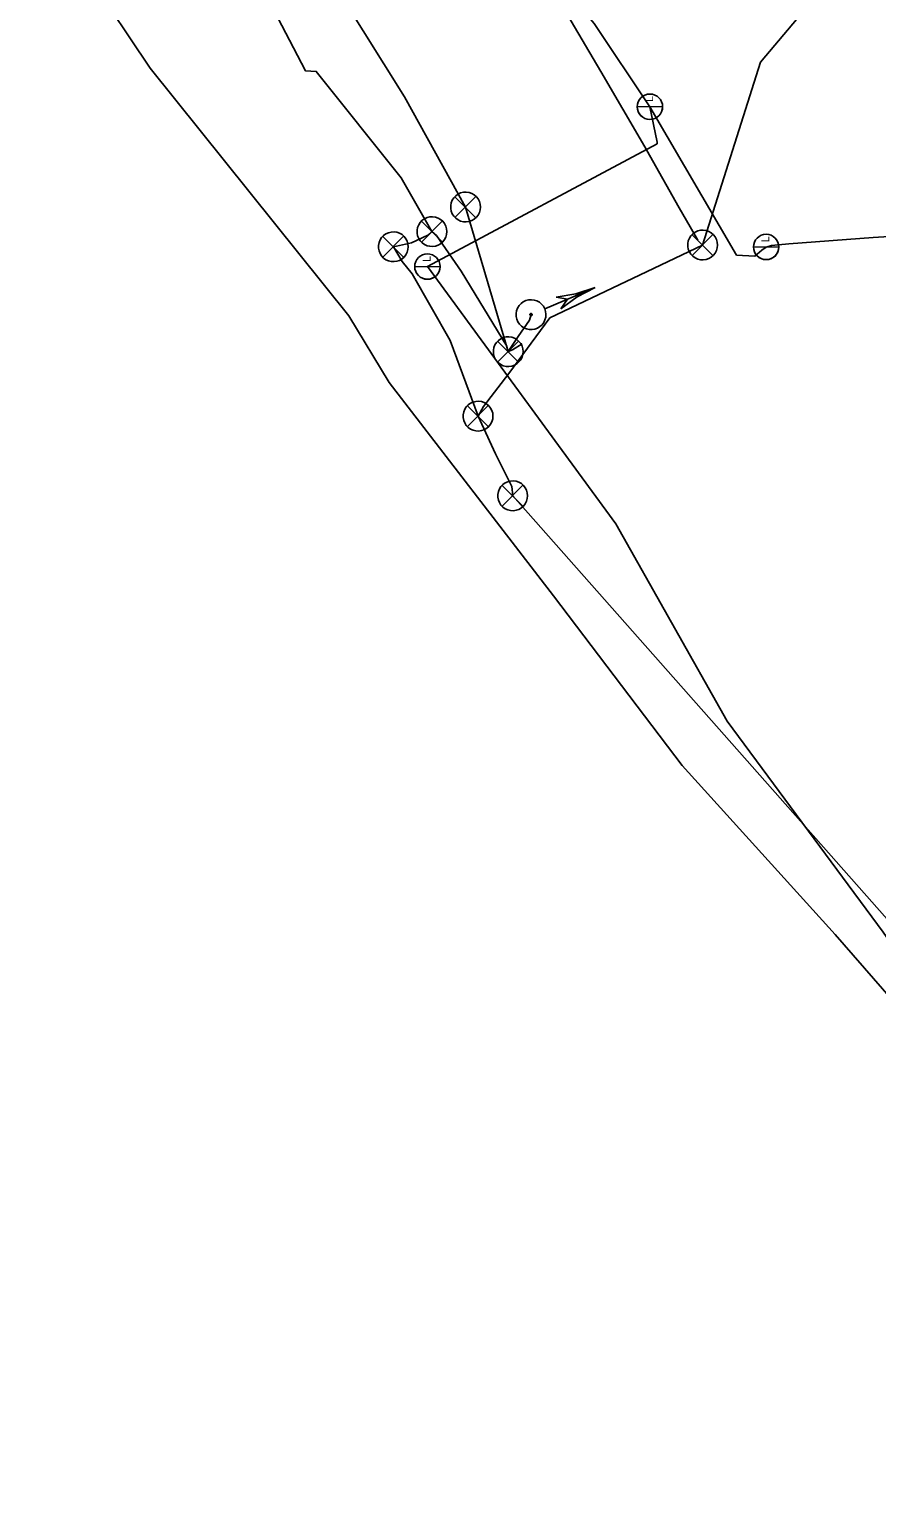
# Model space of a CAD drawing. Extents: x 596028 to 606371, y 330010 to 403088.
# Drawn here: x 604008 to 604195.4, y 338728.3 to 339055.2 of the extents above; entities that cross this region are included whole.
import ezdxf

# ---------------------------------------------------------------- set-up
doc = ezdxf.new("R2010")
doc.units = 0
for name, color, linetype in [('E_FTMS', 7, 'Continuous'), ('E_FTMS_Conduit', 7, 'Continuous'), ('E_LTG', 7, 'Continuous'), ('E_LTG_CID', 7, 'Continuous'), ('E_UTL_FO_UG_QWEST', 7, 'Continuous')]:
    doc.layers.add(name, color=color, linetype=linetype)

# ---------------------------------------------------------------- blocks, each defined once
blk = doc.blocks.new('_U286')
at = {"layer": 'E_LTG'}
blk.add_lwpolyline([(0.001, -0.171), (0.001, 0.172)], dxfattribs=at)
blk.add_circle((0.001, 0), 0.171, dxfattribs=at)
blk.add_arc((0.001, 0), 0.171, 90, 270, dxfattribs=at)
blk.add_text('L', height=0.108, dxfattribs=at).set_placement((0.066, -0.042))

msp = doc.modelspace()

# ---------------------------------------------------------------- linework, layer by layer
at = {"layer": 'E_FTMS'}
for points in [[(604107.76, 339015.89), (604107.7, 339016.52), (604107.53, 339017.12), (604107.24, 339017.68), (604106.85, 339018.17), (604106.38, 339018.58), (604105.83, 339018.89), (604105.24, 339019.1), (604104.62, 339019.19), (604103.99, 339019.16), (604103.38, 339019.01), (604102.81, 339018.75), (604102.3, 339018.39), (604101.87, 339017.93), (604101.53, 339017.41), (604101.3, 339016.82), (604101.18, 339016.21), (604101.18, 339015.58), (604101.3, 339014.96), (604101.53, 339014.38), (604101.87, 339013.85), (604102.3, 339013.4), (604102.81, 339013.04), (604103.38, 339012.77), (604103.99, 339012.63), (604104.62, 339012.6), (604105.24, 339012.69), (604105.83, 339012.89), (604106.38, 339013.21), (604106.85, 339013.62), (604107.24, 339014.11), (604107.53, 339014.67), (604107.7, 339015.27), (604107.76, 339015.89)], [(604106.73, 339018.23), (604102.12, 339013.57)], [(604102.12, 339018.18), (604106.77, 339013.53)], [(604100.32, 339010.46), (604100.26, 339011.09), (604100.09, 339011.69), (604099.8, 339012.25), (604099.41, 339012.74), (604098.94, 339013.15), (604098.39, 339013.46), (604097.8, 339013.67), (604097.18, 339013.76), (604096.55, 339013.73), (604095.94, 339013.58), (604095.37, 339013.32), (604094.86, 339012.96), (604094.43, 339012.5), (604094.09, 339011.98), (604093.86, 339011.39), (604093.74, 339010.78), (604093.74, 339010.15), (604093.86, 339009.53), (604094.09, 339008.95), (604094.43, 339008.42), (604094.86, 339007.97), (604095.37, 339007.61), (604095.94, 339007.34), (604096.55, 339007.2), (604097.18, 339007.17), (604097.8, 339007.26), (604098.39, 339007.46), (604098.94, 339007.78), (604099.41, 339008.19), (604099.8, 339008.68), (604100.09, 339009.24), (604100.26, 339009.84), (604100.32, 339010.46)], [(604099.29, 339012.8), (604094.68, 339008.14)], [(604094.68, 339012.75), (604099.33, 339008.1)], [(604091.78, 339007.1), (604091.72, 339007.73), (604091.55, 339008.33), (604091.26, 339008.89), (604090.87, 339009.38), (604090.4, 339009.79), (604089.85, 339010.1), (604089.26, 339010.31), (604088.64, 339010.4), (604088.01, 339010.37), (604087.4, 339010.22), (604086.83, 339009.96), (604086.32, 339009.6), (604085.89, 339009.14), (604085.55, 339008.61), (604085.32, 339008.03), (604085.2, 339007.42), (604085.2, 339006.79), (604085.32, 339006.17), (604085.55, 339005.59), (604085.89, 339005.06), (604086.32, 339004.61), (604086.83, 339004.24), (604087.4, 339003.98), (604088.01, 339003.84), (604088.64, 339003.81), (604089.26, 339003.9), (604089.85, 339004.1), (604090.4, 339004.41), (604090.87, 339004.82), (604091.26, 339005.32), (604091.55, 339005.88), (604091.72, 339006.48), (604091.78, 339007.1)], [(604090.74, 339009.44), (604086.13, 339004.78)], [(604086.13, 339009.39), (604090.79, 339004.74)], [(604160.22, 339007.49), (604160.16, 339008.12), (604159.99, 339008.72), (604159.7, 339009.28), (604159.31, 339009.77), (604158.84, 339010.18), (604158.3, 339010.49), (604157.7, 339010.7), (604157.08, 339010.79), (604156.45, 339010.76), (604155.85, 339010.61), (604155.27, 339010.35), (604154.76, 339009.99), (604154.33, 339009.53), (604153.99, 339009), (604153.76, 339008.42), (604153.64, 339007.81), (604153.64, 339007.18), (604153.76, 339006.56), (604153.99, 339005.98), (604154.33, 339005.45), (604154.76, 339005), (604155.27, 339004.63), (604155.85, 339004.37), (604156.45, 339004.23), (604157.08, 339004.2), (604157.7, 339004.29), (604158.3, 339004.49), (604158.84, 339004.8), (604159.31, 339005.22), (604159.7, 339005.71), (604159.99, 339006.27), (604160.16, 339006.87), (604160.22, 339007.49)], [(604159.19, 339009.83), (604154.58, 339005.17)], [(604154.58, 339009.78), (604159.23, 339005.13)], [(604121.99, 338993.37), (604121.69, 338993.92), (604121.29, 338994.41), (604120.81, 338994.81), (604120.26, 338995.11), (604119.66, 338995.3), (604119.04, 338995.38), (604118.42, 338995.34), (604117.81, 338995.18), (604117.24, 338994.91), (604116.74, 338994.53), (604116.32, 338994.07), (604115.99, 338993.53), (604115.77, 338992.95), (604115.66, 338992.33), (604115.67, 338991.7), (604115.81, 338991.09), (604116.05, 338990.51), (604116.4, 338989.99), (604116.84, 338989.54), (604117.36, 338989.19), (604117.94, 338988.94), (604118.55, 338988.81), (604119.18, 338988.79), (604119.8, 338988.89), (604120.39, 338989.11), (604120.92, 338989.43), (604121.39, 338989.85), (604121.76, 338990.36), (604122.04, 338990.92), (604122.21, 338991.52), (604122.25, 338992.15), (604122.18, 338992.77), (604121.99, 338993.37)], [(604133.13, 338998.1), (604122.04, 338993.39)], [(604133.13, 338998.1), (604128.89, 338996.68), (604124.49, 338995.93)], [(604127.05, 338995.52), (604124.49, 338995.93)], [(604125.56, 338993.4), (604127.05, 338995.52)], [(604133.13, 338998.1), (604129.16, 338996.04), (604125.57, 338993.39)], [(604119.19, 338992.18), (604119.16, 338992.22), (604119.13, 338992.26), (604119.09, 338992.29), (604119.05, 338992.31), (604119.01, 338992.33), (604118.96, 338992.33), (604118.91, 338992.33), (604118.87, 338992.32), (604118.82, 338992.3), (604118.78, 338992.27), (604118.75, 338992.23), (604118.73, 338992.19), (604118.71, 338992.15), (604118.7, 338992.1), (604118.7, 338992.05), (604118.71, 338992.01), (604118.73, 338991.96), (604118.76, 338991.92), (604118.79, 338991.89), (604118.83, 338991.86), (604118.88, 338991.84), (604118.92, 338991.83), (604118.97, 338991.83), (604119.02, 338991.84), (604119.06, 338991.85), (604119.1, 338991.88), (604119.14, 338991.91), (604119.17, 338991.95), (604119.19, 338991.99), (604119.2, 338992.04), (604119.21, 338992.09), (604119.2, 338992.13), (604119.19, 338992.18)], [(604117.19, 338983.89), (604117.13, 338984.52), (604116.96, 338985.12), (604116.67, 338985.68), (604116.28, 338986.17), (604115.81, 338986.58), (604115.26, 338986.89), (604114.67, 338987.1), (604114.05, 338987.19), (604113.42, 338987.16), (604112.81, 338987.01), (604112.24, 338986.75), (604111.73, 338986.39), (604111.3, 338985.93), (604110.96, 338985.41), (604110.73, 338984.82), (604110.61, 338984.21), (604110.61, 338983.58), (604110.73, 338982.96), (604110.96, 338982.38), (604111.3, 338981.85), (604111.73, 338981.4), (604112.24, 338981.04), (604112.81, 338980.77), (604113.42, 338980.63), (604114.05, 338980.6), (604114.67, 338980.69), (604115.26, 338980.89), (604115.81, 338981.21), (604116.28, 338981.62), (604116.67, 338982.11), (604116.96, 338982.67), (604117.13, 338983.27), (604117.19, 338983.89)], [(604116.16, 338986.23), (604111.55, 338981.57)], [(604111.55, 338986.18), (604116.2, 338981.53)], [(604110.53, 338969.61), (604110.47, 338970.24), (604110.29, 338970.84), (604110, 338971.4), (604109.62, 338971.89), (604109.14, 338972.3), (604108.6, 338972.62), (604108.01, 338972.82), (604107.39, 338972.91), (604106.76, 338972.88), (604106.15, 338972.73), (604105.58, 338972.47), (604105.07, 338972.11), (604104.63, 338971.65), (604104.3, 338971.13), (604104.06, 338970.54), (604103.94, 338969.93), (604103.94, 338969.3), (604104.06, 338968.68), (604104.3, 338968.1), (604104.63, 338967.57), (604105.07, 338967.12), (604105.58, 338966.76), (604106.15, 338966.5), (604106.76, 338966.35), (604107.39, 338966.32), (604108.01, 338966.41), (604108.6, 338966.61), (604109.14, 338966.93), (604109.62, 338967.34), (604110, 338967.83), (604110.29, 338968.39), (604110.47, 338968.99), (604110.53, 338969.61)], [(604109.49, 338971.95), (604104.88, 338967.29)], [(604104.88, 338971.9), (604109.53, 338967.25)], [(604118.19, 338951.98), (604118.13, 338952.61), (604117.96, 338953.21), (604117.67, 338953.77), (604117.28, 338954.26), (604116.81, 338954.67), (604116.26, 338954.98), (604115.67, 338955.19), (604115.05, 338955.28), (604114.42, 338955.25), (604113.81, 338955.1), (604113.24, 338954.84), (604112.73, 338954.48), (604112.3, 338954.02), (604111.96, 338953.49), (604111.73, 338952.91), (604111.61, 338952.3), (604111.61, 338951.67), (604111.73, 338951.05), (604111.96, 338950.47), (604112.3, 338949.94), (604112.73, 338949.49), (604113.24, 338949.12), (604113.81, 338948.86), (604114.42, 338948.72), (604115.05, 338948.69), (604115.67, 338948.78), (604116.26, 338948.98), (604116.81, 338949.29), (604117.28, 338949.71), (604117.67, 338950.2), (604117.96, 338950.76), (604118.13, 338951.36), (604118.19, 338951.98)], [(604117.16, 338954.32), (604112.55, 338949.66)], [(604112.55, 338954.27), (604117.2, 338949.62)]]:
    msp.add_lwpolyline(points, dxfattribs=at)
at = {"layer": 'E_FTMS_Conduit'}
for points in [[(604113.89, 338983.89), (604104.46, 339015.89), (604090.96, 339040.27), (604077.26, 339062.3), (604070.63, 339081.86), (604055.37, 339128.14), (604048.99, 339151), (604037.26, 339191.41), (604036.51, 339193.09), (604036.31, 339194.34), (604031.92, 339203.07), (604031.51, 339204.01), (604023.3, 339242.34), (604034.29, 339302.44)], [(604114.89, 338951.98), (604114.71, 338954.06), (604111.09, 338961.25), (604108.03, 338967.81), (604107.23, 338969.61), (604101.02, 338986.39), (604092.64, 339001.09), (604090.42, 339003.87), (604088.48, 339007.1), (604092.52, 339007.97), (604096.15, 339009.66), (604097.02, 339010.46), (604090.2, 339022.33), (604071.41, 339045.9), (604069.03, 339046.05), (604046.26, 339089.82)], [(604107.23, 338969.61), (604108.46, 338971.77), (604114.04, 338979.08), (604123.12, 338991.37), (604156.9, 339007.45), (604169.73, 339047.96), (604189.24, 339071.12), (604191.75, 339074.79)], [(604155.89, 339008.54), (604154.16, 339011.54), (604151.73, 339015.73), (604145.16, 339027.38), (604144.11, 339029.2), (604134.43, 339045.93), (604121.03, 339068.62)], [(604097.02, 339010.46), (604098, 339009.56), (604103.51, 339001.68), (604113.6, 338985.12), (604113.89, 338983.89)], [(604113.89, 338983.89), (604116.14, 338987.21), (604118.61, 338990.87), (604118.95, 338992.08)], [(604292.05, 338601.41), (604273.29, 338719.32), (604255.92, 338774.24), (604233.24, 338818.17), (604114.89, 338951.98)]]:
    msp.add_lwpolyline(points, dxfattribs=at)
at = {"layer": 'E_LTG_CID'}
msp.add_line((604146.89, 339029.9), (604096.01, 339002.71), dxfattribs=at)
for points in [[(604146.89, 339029.9), (604146.87, 339030.26), (604145.25, 339038.09), (604132.95, 339056.55), (604122.27, 339069.3), (604109.66, 339096.83), (604097.38, 339128.84), (604088.94, 339157.84), (604080.55, 339185.67), (604082.3, 339195.71), (604082.73, 339213.69), (604082.53, 339214.94)], [(604294.42, 339025.92), (604226.93, 339010.91), (604225.04, 339011.09), (604194.7, 339009.16), (604175.97, 339007.72), (604172.17, 339007.37), (604170.97, 339007.05), (604170.02, 339006.34), (604168.49, 339005.05), (604164.44, 339005.28), (604145.25, 339038.09)], [(604230.78, 338806.58), (604229.94, 338807.94), (604196.91, 338855.38), (604162.36, 338902.09), (604137.73, 338945.81), (604096.01, 339002.71)], [(604116.96, 338985.6), (604114.88, 338984.31), (604113.89, 338983.89)]]:
    msp.add_lwpolyline(points, dxfattribs=at)
at = {"layer": 'E_UTL_FO_UG_QWEST'}
msp.add_lwpolyline([(604265.37, 338681.02), (604255.89, 338741.85), (604241.59, 338781.41), (604236.84, 338788.31), (604222.2, 338813.62), (604186.27, 338854.85), (604152.41, 338892.26), (604123.95, 338929.81), (604087.55, 338977.05), (604078.65, 338991.8), (604034.65, 339046.66), (604007.98, 339086.56)], dxfattribs=at)

# ---------------------------------------------------------------- block references
at = {"layer": 'E_FTMS', "xscale": 16.40416666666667, "yscale": 16.40416666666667, "rotation": 89.38304225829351}
for p in [(604145.26, 339038.08), (604170.98, 339007.04), (604096.02, 339002.7)]:
    msp.add_blockref('_U286', p, dxfattribs=at)

doc.saveas('drawing.dxf')
